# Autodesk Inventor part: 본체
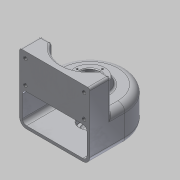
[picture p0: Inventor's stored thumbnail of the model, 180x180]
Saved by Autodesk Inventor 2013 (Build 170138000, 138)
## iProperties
Created: 2015-02
Part Number: 본체
Material: 알루미늄 6061
Document SubType Name: Modeling
Designer: Administrator
Density: 2.71 g/cm^3
Mass: 575.568 g
Surface Area: 707.538 cm^2
Volume: 212.387 cm^3
Author: Administrator
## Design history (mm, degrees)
sketch "스케치1"
  geometry: L1 (50, -50)-(-50, -50); L2 (-50, -50)-(-50, 50); L3 (-50, 50)-(50, 50); L4 (50, 50)-(50, -50); L5 (50, -50)-(-50, 50); L6 (-50, -50)-(50, 50); 1 further point
  constraints: 12 end point, 2 midpoint, 2 parallel, 1 horizontal, 1 perpendicular
  dimensions: "d0" = 100 distance of L2.end L3.end; "d1" = 100 distance of L1.end L2.end
extrude "돌출1" new body sketch "스케치1" distance "d2" = 50; taper "d3" = 0 deg
fillet "모깎기1" dims "d4" = 50
feature "쉘1" dims "d5" = 4
sketch "스케치2"
  geometry: L1 (-50, -50)-(50, -50) reference; L2 (50, -50)-(50, 0) reference; L3 (50, -20)-(50, -50); L4 (0, 0)-(0, -65.816); L5 (-50, -20)-(-50, -50); L6 (50, -20)-(34.641, -20); L7 (-50, -20)-(-34.641, -20); L8 (-50, -50)-(50, -50); A1 r 50 centre (0, 0) between (50, 0) and (-50, 0) reference; A2 r 40 centre (0, 0) between (-34.641, -20) and (34.641, -20)
  constraints: 12 end point, 3 collinear, 2 point on circle, 2 symmetric about line, 1 centre point, 1 coincident, 1 parallel, 1 perpendicular, 1 point on line
  dimensions: "d6" = 80 diameter of A2; "d8" = 50 distance between parallel lines of L4 L3; "d9" = 30 distance between parallel lines of L1 L7
extrude "돌출2" join sketch "스케치2" distance "d10" = 45; taper "d11" = 0 deg
sketch "스케치3"
  geometry: C1 r 25 at (0, 0); A1 r 50 centre (0, 0) between (50, 0) and (-50, 0) reference
  constraints: 1 centre point, 1 coincident
  dimensions: "d12" = 50 diameter of C1
extrude "돌출3" join sketch "스케치3" distance "d14" = 10; taper "d15" = 0 deg
sketch "스케치4"
  geometry: C1 r 20 at (0, 0); A1 r 50 centre (0, 0) between (50, 0) and (-50, 0) reference
  constraints: 1 centre point, 1 coincident
  dimensions: "d16" = 40 diameter of C1
extrude "돌출4" join sketch "스케치4" distance "d18" = 9; taper "d19" = 0 deg
feature "면 기울기1" dims angle "d20" = 20 deg
hole "구멍1" diameter "d23" = 28; stored, may be unused: countersink angle "d27" = 90 deg, drill point angle "d29" = 0 deg; dims "d21" = 10, "d22" = 10, "d24" = 6, "d25" = 4, "d26" = 2, "d28" = 10
hole "구멍2" diameter "d32" = 20; stored, may be unused: countersink angle "d36" = 90 deg, drill point angle "d38" = 0 deg; dims "d30" = 10, "d31" = 10, "d33" = 6, "d34" = 4, "d35" = 2, "d37" = 4
hole "구멍3" diameter "d41" = 28; stored, may be unused: countersink angle "d45" = 90 deg, drill point angle "d47" = 0 deg; dims "d39" = 10, "d40" = 10, "d42" = 6, "d43" = 4, "d44" = 2, "d46" = 8
hole "구멍4" diameter "d50" = 20; stored, may be unused: countersink angle "d54" = 90 deg, drill point angle "d56" = 0 deg; dims "d48" = 10, "d49" = 10, "d51" = 6, "d52" = 4, "d53" = 2, "d55" = 2
fillet "모깎기2" dims "d57" = 10
fillet "모깎기3" dims "d58" = 0.3
fillet "모깎기4" dims "d59" = 3
fillet "모깎기5" dims "d60" = 3
chamfer "모따기1" distance "d61" = 1; stored, may be unused: second distance "d62" = 2, angle "d63" = 45 deg
fillet "모깎기6" dims "d64" = 6
sketch "스케치5"
  geometry: L1 (-7, 95)-(87, 95) reference; L2 (-10, 10)-(-10, 92) reference; 2 further points
  dimensions: "d65" = 9 distance from line of L1 point (-1.75, 86); "d66" = 8.25 distance from line of L2 point (-1.75, 86)
hole "구멍5" sketch "스케치5" at (-1.75, 86) diameter "d67" = 5.134; stored, may be unused: countersink angle "d71" = 90 deg, drill point angle "d73" = 118 deg; dims "d68" = 10, "d69" = 4, "d70" = 2, "d72" = 13
sketch "스케치6" dims "d80" = 36
  geometry: C1 r 21.36 at (0, 0) reference; C2 r 15 at (0, 0) reference; 2 further points
  constraints: 2 vertical alignment, 1 coincident, 2 other
hole "구멍6" sketch "스케치6" at (0, 18) diameter "d82" = 2.459; stored, may be unused: countersink angle "d86" = 90 deg, drill point angle "d88" = 118 deg; dims "d83" = 6, "d84" = 4, "d85" = 2, "d87" = 9
node "작업 평면1"
sketch "스케치7"
  geometry: L1 (40, 0)-(-40, 0) reference; 2 further points
  constraints: 1 vertical alignment, 1 other
  dimensions: "d92" = 25 distance from line of L1 point (0, 25)
feature "엠보싱1" sketch "스케치7" dims "d0" = 100, "d1" = 100, "d6" = 80, "d8" = 50, "d9" = 30, "d93" = 0.5, "d94" = 0
node "솔리드1"
pattern_linear "직사각형 패턴1" dims "d76" = 83.5, "d79" = 33
pattern_circular "원형 패턴1" dims angle "d90" = 360 deg
